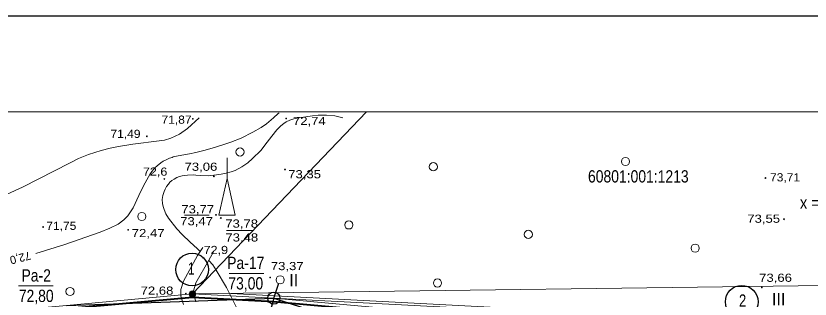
# Model space of a CAD drawing. Extents: x 628176 to 629009, y 6439913 to 6440496.
# Drawn here: x 628531.9 to 628726.4, y 6440426.6 to 6440495.9 of the extents above; entities that cross this region are included whole.
import ezdxf
from ezdxf.enums import TextEntityAlignment as Align

# ---------------------------------------------------------------- set-up
doc = ezdxf.new("R2010")
doc.units = 0
doc.header["$LTSCALE"] = 0.8
doc.linetypes.add('MEDIUM_DASHED', pattern=[4.5, 3, -1.5])
for name, color, linetype, lineweight in [('1', 7, 'Continuous', 13), ('10', 7, 'Continuous', 25), ('11', 7, 'Continuous', 13), ('12', 7, 'Continuous', 13), ('14', 7, 'Continuous', 25), ('21', 7, 'MEDIUM_DASHED', 35), ('3', 7, 'Continuous', 13), ('50', 7, 'Continuous', 13), ('6', 7, 'Continuous', 13)]:
    doc.layers.add(name, color=color, linetype=linetype, lineweight=lineweight)
doc.layers.add('23', color=7, linetype='Continuous')
doc.layers.add('4', color=7, linetype='Continuous')

msp = doc.modelspace()

# ---------------------------------------------------------------- hatches: boundary and pattern name
at = {"layer": '1'}
for points in [[(628575.3867, 6440470.7513, 1), (628575.1867, 6440470.7513, 1)], [(628598.2123, 6440470.8336, 1), (628598.0123, 6440470.8336, 1)], [(628564.13, 6440466.4538, 1), (628563.93, 6440466.4538, 1)], [(628597.9416, 6440458.3338, 1), (628597.7416, 6440458.3338, 1)], [(628568.3893, 6440456.0096, 1), (628568.1893, 6440456.0096, 1)], [(628580.5414, 6440456.6638, 1), (628580.3414, 6440456.6638, 1)], [(628715.5574, 6440456.2675, 1), (628715.3574, 6440456.2675, 1)], [(628581.0535, 6440447.2671, 1), (628580.8535, 6440447.2671, 1)], [(628582.2003, 6440446.4847, 1), (628582.0003, 6440446.4847, 1)], [(628720.1098, 6440446.1696, 1), (628719.9098, 6440446.1696, 1)], [(628538.743, 6440444.276, 1), (628538.543, 6440444.276, 1)], [(628559.5256, 6440443.5875, 1), (628559.3256, 6440443.5875, 1)], [(628577.9044, 6440436.7574, 1), (628577.7044, 6440436.7574, 1)], [(628594.3203, 6440431.9219, 1), (628594.1203, 6440431.9219, 1)], [(628714.6839, 6440429.4873, 1), (628714.4839, 6440429.4873, 1)], [(628573.6366, 6440427.9725, 1), (628573.4366, 6440427.9725, 1)]]:
    msp.add_hatch(color=256, dxfattribs=at).paths.add_polyline_path(points)
at = {"layer": '10'}
msp.add_hatch(color=256, dxfattribs=at).paths.add_polyline_path([(628575.94, 6440427.91, 1), (628574.44, 6440427.91, 1)])

# ---------------------------------------------------------------- linework, layer by layer
at = {"layer": '1'}
for p, q in [((628583.66, 6440456.17), (628583.66, 6440461.17)), ((628573.24, 6440447.14), (628579.24, 6440447.14)), ((628583.49, 6440443.4), (628590.02, 6440443.4))]:
    msp.add_line(p, q, dxfattribs=at)
msp.add_lwpolyline([(628581.66, 6440447.17), (628583.66, 6440456.17), (628585.66, 6440447.17)], close=True, dxfattribs=at)
for points in [[(628572.35, 6440429), (628573, 6440431), (628576.42, 6440437.34), (628577.72, 6440439.25)], [(628576.01, 6440426), (628575.38, 6440428.31), (628576, 6440430.63), (628579.19, 6440436.17), (628580.37, 6440438.23)], [(628572.35, 6440429), (628572.35, 6440427.37), (628573, 6440425.35)]]:
    msp.add_lwpolyline(points, dxfattribs=at)
for centre, radius in [((628575.2867, 6440470.7513), 0.1), ((628598.1123, 6440470.8336), 0.1), ((628564.03, 6440466.4538), 0.1), ((628586.8374, 6440462.6312), 1), ((628634.1476, 6440459.0118), 1), ((628681.1992, 6440460.3044), 1), ((628597.8416, 6440458.3338), 0.1), ((628568.2893, 6440456.0096), 0.1), ((628580.4414, 6440456.6638), 0.1), ((628715.4574, 6440456.2675), 0.1), ((628562.7945, 6440446.8611), 1), ((628580.9535, 6440447.2671), 0.1), ((628582.1003, 6440446.4847), 0.1), ((628720.0098, 6440446.1696), 0.1), ((628538.643, 6440444.276), 0.1), ((628613.4655, 6440444.7929), 1), ((628559.4256, 6440443.5875), 0.1), ((628657.4149, 6440442.4662), 1), ((628698.2619, 6440439.1054), 1), ((628577.8044, 6440436.7574), 0.1), ((628594.2203, 6440431.9219), 0.1), ((628596.6614, 6440431.3496), 1), ((628635.1817, 6440430.574), 1), ((628545.2148, 6440428.5058), 1), ((628714.5839, 6440429.4873), 0.1), ((628573.5366, 6440427.9725), 0.1)]:
    msp.add_circle(centre, radius, dxfattribs=at)
at = {"layer": '10'}
for centre, radius in [((628575.0864, 6440433.8784), 4), ((628575.19, 6440427.91), 0.75), ((628709.6526, 6440426.0059), 4)]:
    msp.add_circle(centre, radius, dxfattribs=at)
at = {"layer": '11'}
msp.add_line((628595.11, 6440426.87), (628709.76, 6440416.52), dxfattribs=at)
for points in [[(628393.19, 6440398.39), (628410.48, 6440417.82), (628464.14, 6440417.8), (628544.36, 6440425.1), (628575.19, 6440427.91), (628595.11, 6440426.87)], [(628595.11, 6440426.87), (628573.75, 6440350.05), (628485.59, 6440282.78), (628547.63, 6440210.77)], [(628595.11, 6440426.87), (628713.84, 6440420.66), (628709.76, 6440416.52)]]:
    msp.add_lwpolyline(points, dxfattribs=at)
at = {"layer": '12'}
for p, q in [((628584.14, 6440432.94), (628592.63, 6440432.94)), ((628532.6, 6440429.87), (628541.09, 6440429.87))]:
    msp.add_line(p, q, dxfattribs=at)
at = {"layer": '12', "lineweight": 25}
msp.add_circle((628595.106, 6440426.8687), 1.5, dxfattribs=at)
at = {"layer": '14'}
msp.add_line((628595.11, 6440426.87), (628596.29, 6440430.58), dxfattribs=at)
for points in [[(628595.11, 6440426.87), (628573.75, 6440350.05), (628485.59, 6440282.78)], [(628544.36, 6440425.1), (628595.11, 6440426.87), (628648, 6440409.69), (628709.76, 6440416.52)]]:
    msp.add_lwpolyline(points, dxfattribs=at)
at = {"layer": '21', "linetype": 'Continuous', "lineweight": 40}
msp.add_lwpolyline([(628544.47, 6440424.31), (628575.21, 6440427.11), (628595.05, 6440426.07), (628708.01, 6440415.87)], dxfattribs=at)
at = {"layer": '3'}
for p, q in [((628601.22, 6440471), (628604.55, 6440471.45)), ((628604.55, 6440471.45), (628605.99, 6440471.59)), ((628605.99, 6440471.59), (628608, 6440471.65)), ((628599.97, 6440470.74), (628599, 6440470.4)), ((628601.22, 6440471), (628599.97, 6440470.74)), ((628560.58, 6440464.54), (628567, 6440465.31)), ((628568.33, 6440465.52), (628567, 6440465.31)), ((628574.44, 6440462.19), (628571.71, 6440461.67)), ((628576, 6440462.52), (628574.44, 6440462.19)), ((628570.49, 6440461.4), (628571.71, 6440461.67)), ((628564.72, 6440457.12), (628565.24, 6440457.86)), ((628585.62, 6440458.1), (628584.66, 6440457.75)), ((628564.38, 6440456.58), (628563.19, 6440454.37)), ((628564.38, 6440456.58), (628564.72, 6440457.12)), ((628575.33, 6440457), (628576, 6440456.97)), ((628576, 6440456.97), (628577.25, 6440456.88)), ((628577.25, 6440456.88), (628579, 6440456.83)), ((628584.66, 6440457.75), (628583.42, 6440457.43)), ((628568.22, 6440448.55), (628568, 6440449.27)), ((628571.37, 6440443.84), (628572.66, 6440442.46)), ((628536.83, 6440437.77), (628543.91, 6440440)), ((628586.79, 6440423), (628583.48, 6440429.52))]:
    msp.add_line(p, q, dxfattribs=at)
for points in [[(628576, 6440462.52), (628578, 6440463.01), (628580, 6440463.57), (628582.64, 6440464.36), (628584.6, 6440465), (628587.13, 6440466), (628590, 6440467.43), (628592, 6440468.61), (628593.29, 6440469.53), (628595.06, 6440471), (628596.17, 6440472), (628596.39, 6440472.18)], [(628612.03, 6440471), (628610, 6440471.45), (628608, 6440471.65)], [(628568.33, 6440465.52), (628569.88, 6440466), (628572.02, 6440467), (628574, 6440468.35), (628576.85, 6440471)], [(628599, 6440470.4), (628598.16, 6440470), (628597.54, 6440469.58), (628596.83, 6440469), (628595.85, 6440468), (628594.62, 6440466.49), (628593.51, 6440465), (628591.88, 6440463), (628589.89, 6440461), (628588.72, 6440460), (628587.27, 6440459), (628585.62, 6440458.1)], [(628547.31, 6440461), (628549.73, 6440462), (628552.8, 6440463), (628555, 6440463.59), (628557.04, 6440464), (628560.58, 6440464.54)], [(628422, 6440418.57), (628429.42, 6440420), (628438.21, 6440421), (628450.1, 6440422), (628459.07, 6440423), (628466.71, 6440424), (628472.14, 6440425), (628475.51, 6440426), (628477.87, 6440427), (628479.64, 6440428), (628483.9, 6440431), (628486.91, 6440433), (628490.26, 6440435), (628497.84, 6440439), (628499.78, 6440440), (628501.87, 6440441), (628506.4, 6440443), (628526.88, 6440451), (628533.59, 6440454), (628545.23, 6440460), (628547.31, 6440461)], [(628565.24, 6440457.86), (628565.64, 6440458.35), (628566, 6440458.73), (628566.5, 6440459.21), (628567.45, 6440460)], [(628567.45, 6440460), (628568, 6440460.37), (628568.54, 6440460.64)], [(628570.49, 6440461.4), (628570.2, 6440461.31), (628569.58, 6440461.09), (628568.54, 6440460.64)], [(628575.33, 6440457), (628574, 6440456.97), (628573.23, 6440456.9), (628572.68, 6440456.8), (628572, 6440456.62), (628571.32, 6440456.35), (628570.69, 6440456), (628570.16, 6440455.63), (628569.67, 6440455.21), (628569.28, 6440454.78), (628568.86, 6440454.22), (628568.47, 6440453.56), (628568.22, 6440453), (628567.93, 6440452), (628567.78, 6440451), (628567.83, 6440450.06), (628568, 6440449.27)], [(628583.42, 6440457.43), (628582.22, 6440457.16), (628581.07, 6440457), (628579, 6440456.83)], [(628543.91, 6440440), (628552.57, 6440443), (628554.97, 6440444), (628556.98, 6440445), (628558.38, 6440446), (628559.33, 6440447), (628560.66, 6440449), (628562.09, 6440452), (628563.19, 6440454.37)], [(628568.22, 6440448.55), (628568.66, 6440447.53), (628569.31, 6440446.46), (628571.37, 6440443.84)], [(628572.66, 6440442.46), (628574.59, 6440440.6), (628576.37, 6440439), (628577.09, 6440438.32)], [(628579.16, 6440436.12), (628580.13, 6440435), (628581, 6440433.7), (628583.48, 6440429.52)]]:
    msp.add_lwpolyline(points, dxfattribs=at)
at = {"layer": '50', "lineweight": 25}
msp.add_lwpolyline([(628178.27, 6440495.9), (629008.51, 6440495.9), (629008.51, 6439918.47), (628178.27, 6439918.47)], close=True, dxfattribs=at)
at = {"layer": '50'}
msp.add_lwpolyline([(628214.18, 6440472.45), (628760.23, 6440472.45), (628760.23, 6440028.67), (628214.18, 6440028.67)], close=True, dxfattribs=at)
at = {"layer": '6'}
for p, q in [((628575.22, 6440428.51), (628575.74, 6440428.48)), ((628584.56, 6440428.02), (628714.07, 6440421.25))]:
    msp.add_line(p, q, dxfattribs=at)
msp.add_lwpolyline([(628617.76, 6440472.45), (628575.19, 6440427.91), (628575.26, 6440427.9), (628575.26, 6440427.9), (628748.21, 6440430.21), (628751.85, 6440427.4), (628760.23, 6440437.07)], dxfattribs=at)

# ---------------------------------------------------------------- texts
at = {"layer": '1'}
for s, width, p in [('71,87', 1.1, (628567.6, 6440469.53)), ('72,74', 1.2, (628599.79, 6440469.21)), ('71,49', 1.1, (628555.1, 6440466.06)), ('73,06', 1.2, (628573.24, 6440458.02)), ('72,6', 1.15, (628563.04, 6440456.82)), ('73,35', 1.2, (628598.62, 6440456.19)), ('73,71', 1.1, (628716.59, 6440455.43)), ('73,77', 1.2, (628572.45, 6440447.62)), ('73,47', 1.2, (628572.17, 6440444.69)), ('73,78', 1.2, (628583.21, 6440444.12)), ('73,55', 1.2, (628711.02, 6440445.31)), ('71,75', 1.1, (628539.39, 6440443.58)), ('72,47', 1.2, (628560.32, 6440441.8)), ('73,48', 1.2, (628583.24, 6440440.73)), ('72,9', 1.15, (628577.91, 6440437.66)), ('73,37', 1.2, (628594.37, 6440433.73)), ('73,66', 1.2, (628713.93, 6440430.87)), ('72,68', 1.2, (628562.48, 6440427.72))]:
    msp.add_text(s, height=2, dxfattribs=dict(at, width=width)).set_placement(p)
at = {"layer": '10'}
for s, width, p in [('1', 0.7, (628574.88, 6440432.64)), ('2', 0.8, (628709.87, 6440424.79))]:
    msp.add_text(s, height=3, dxfattribs=dict(at, width=width)).set_placement(p, align=Align.CENTER)
at = {"layer": '12', "width": 0.85}
for s, p in [('Pa-17', (628588.225, 6440434)), ('Pa-2', (628536.925, 6440430.94)), ('73,00', (628588.225, 6440429)), ('72,80', (628536.925, 6440425.94))]:
    msp.add_text(s, height=3, dxfattribs=at).set_placement(p, align=Align.CENTER)
at = {"layer": '14'}
for s, p in [('II', (628599.985, 6440429.77)), ('III', (628718.71, 6440425.13))]:
    msp.add_text(s, height=3, dxfattribs=at).set_placement(p, align=Align.CENTER)
at = {"layer": '23', "width": 0.85}
msp.add_text('60801:001:1213', height=3, dxfattribs=at).set_placement((628672.02, 6440455.16))
at = {"layer": '3'}
msp.add_text('72,0', height=2, rotation=194.352, dxfattribs=at).set_placement((628535.33, 6440438.33))
at = {"layer": '4', "width": 0.9}
msp.add_text('x = 6440450', height=3, dxfattribs=at).set_placement((628723.9, 6440448.73))

doc.saveas('drawing.dxf')
